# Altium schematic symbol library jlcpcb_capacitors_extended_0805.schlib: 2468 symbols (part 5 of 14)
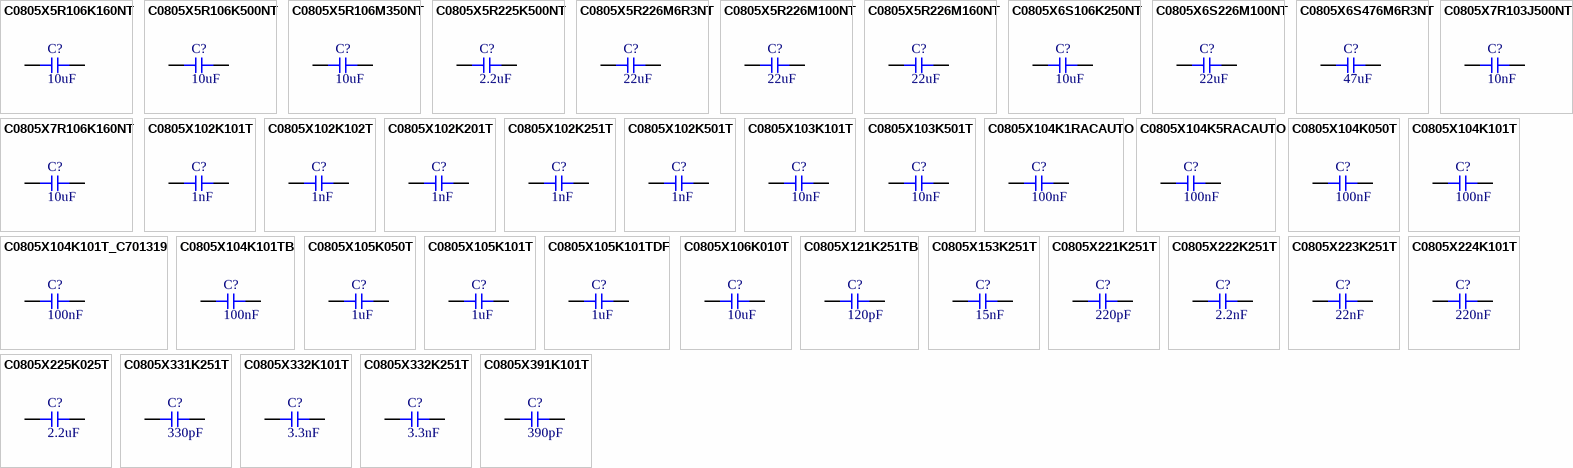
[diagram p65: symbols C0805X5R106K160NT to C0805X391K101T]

## C0805X5R106K500NT
designator C?  Capacitance: 10uF  (hidden comment: *)
Capacitor, Ceramic (MLCC), 10uF, ±10%, 50V, ±10%, SMD 0805; Manufacturer: SANYEAR; Manufacturer Part Number: C0805X5R106K500NT
footprint CAP-0805 (0805 (2012M) Capacitor)
pins: 1, 2

## C0805X5R106M350NT
designator C?  Capacitance: 10uF  (hidden comment: *)
Capacitor, Ceramic (MLCC), 10uF, ±20%, 35V, ±20%, SMD 0805; Manufacturer: SANYEAR; Manufacturer Part Number: C0805X5R106M350NT
footprint CAP-0805 (0805 (2012M) Capacitor)
pins: 1, 2

## C0805X5R225K500NT
designator C?  Capacitance: 2.2uF  (hidden comment: *)
Capacitor, Ceramic (MLCC), 2.2uF, ±10%, 50V, X5R, ±10%, SMD 0805; Manufacturer: SANYEAR; Manufacturer Part Number: C0805X5R225K500NT
footprint CAP-0805 (0805 (2012M) Capacitor)
pins: 1, 2

## C0805X5R226M6R3NT
designator C?  Capacitance: 22uF  (hidden comment: *)
Capacitor, Ceramic (MLCC), 22uF, ±20%, 6.3V, X5R, ±20%, SMD 0805; Manufacturer: SANYEAR; Manufacturer Part Number: C0805X5R226M6R3NT
footprint CAP-0805 (0805 (2012M) Capacitor)
pins: 1, 2

## C0805X5R226M100NT
designator C?  Capacitance: 22uF  (hidden comment: *)
Capacitor, Ceramic (MLCC), 22uF, ±20%, 10V, X5R, ±20%, SMD 0805; Manufacturer: SANYEAR; Manufacturer Part Number: C0805X5R226M100NT
footprint CAP-0805 (0805 (2012M) Capacitor)
pins: 1, 2

## C0805X5R226M160NT
designator C?  Capacitance: 22uF  (hidden comment: *)
Capacitor, Ceramic (MLCC), 22uF, ±20%, 16V, X5R, ±20%, SMD 0805; Manufacturer: SANYEAR; Manufacturer Part Number: C0805X5R226M160NT
footprint CAP-0805 (0805 (2012M) Capacitor)
pins: 1, 2

## C0805X6S106K250NT
designator C?  Capacitance: 10uF  (hidden comment: *)
Capacitor, Ceramic (MLCC), 10uF, ±10%, 25V, ±10%, SMD 0805; Manufacturer: SANYEAR; Manufacturer Part Number: C0805X6S106K250NT
footprint CAP-0805 (0805 (2012M) Capacitor)
pins: 1, 2

## C0805X6S226M100NT
designator C?  Capacitance: 22uF  (hidden comment: *)
Capacitor, Ceramic (MLCC), 22uF, ±20%, 10V, ±20%, SMD 0805; Manufacturer: SANYEAR; Manufacturer Part Number: C0805X6S226M100NT
footprint CAP-0805 (0805 (2012M) Capacitor)
pins: 1, 2

## C0805X6S476M6R3NT
designator C?  Capacitance: 47uF  (hidden comment: *)
Capacitor, Ceramic (MLCC), 47uF, ±20%, 6.3V, ±20%, SMD 0805; Manufacturer: SANYEAR; Manufacturer Part Number: C0805X6S476M6R3NT
footprint CAP-0805 (0805 (2012M) Capacitor)
pins: 1, 2

## C0805X7R103J500NT
designator C?  Capacitance: 10nF  (hidden comment: *)
Capacitor, Ceramic (MLCC), 10nF, ±5%, 50V, ±5%, SMD 0805; Manufacturer: SANYEAR; Manufacturer Part Number: C0805X7R103J500NT
footprint CAP-0805 (0805 (2012M) Capacitor)
pins: 1, 2

## C0805X7R106K160NT
designator C?  Capacitance: 10uF  (hidden comment: *)
Capacitor, Ceramic (MLCC), 10uF, ±10%, 16V, ±10%, SMD 0805; Manufacturer: SANYEAR; Manufacturer Part Number: C0805X7R106K160NT
footprint CAP-0805 (0805 (2012M) Capacitor)
pins: 1, 2

## C0805X102K101T
designator C?  Capacitance: 1nF  (hidden comment: *)
Capacitor, Ceramic (MLCC), 1nF, ±10%, 100V, X7R, ±10%, SMD 0805; Manufacturer: IHHEC(HOLY STONE ENTERPRISE CO., LTD); Manufacturer Part Number: C0805X102K101T
footprint CAP-0805 (0805 (2012M) Capacitor)
pins: 1, 2

## C0805X102K102T
designator C?  Capacitance: 1nF  (hidden comment: *)
Capacitor, Ceramic (MLCC), 1nF, ±10%, 1kV, X7R, ±10%, SMD 0805; Manufacturer: IHHEC(HOLY STONE ENTERPRISE CO., LTD); Manufacturer Part Number: C0805X102K102T
footprint CAP-0805 (0805 (2012M) Capacitor)
pins: 1, 2

## C0805X102K201T
designator C?  Capacitance: 1nF  (hidden comment: *)
Capacitor, Ceramic (MLCC), 1nF, ±10%, 200V, X7R, ±10%, SMD 0805; Manufacturer: IHHEC(HOLY STONE ENTERPRISE CO., LTD); Manufacturer Part Number: C0805X102K201T
footprint CAP-0805 (0805 (2012M) Capacitor)
pins: 1, 2

## C0805X102K251T
designator C?  Capacitance: 1nF  (hidden comment: *)
Capacitor, Ceramic (MLCC), 1nF, ±10%, 250V, X7R, ±10%, SMD 0805; Manufacturer: IHHEC(HOLY STONE ENTERPRISE CO., LTD); Manufacturer Part Number: C0805X102K251T
footprint CAP-0805 (0805 (2012M) Capacitor)
pins: 1, 2

## C0805X102K501T
designator C?  Capacitance: 1nF  (hidden comment: *)
Capacitor, Ceramic (MLCC), 1nF, ±10%, 500V, X7R, ±10%, SMD 0805; Manufacturer: IHHEC(HOLY STONE ENTERPRISE CO., LTD); Manufacturer Part Number: C0805X102K501T
footprint CAP-0805 (0805 (2012M) Capacitor)
pins: 1, 2

## C0805X103K101T
designator C?  Capacitance: 10nF  (hidden comment: *)
Capacitor, Ceramic (MLCC), 10nF, ±10%, 100V, X7R, ±10%, SMD 0805; Manufacturer: IHHEC(HOLY STONE ENTERPRISE CO., LTD); Manufacturer Part Number: C0805X103K101T
footprint CAP-0805 (0805 (2012M) Capacitor)
pins: 1, 2

## C0805X103K501T
designator C?  Capacitance: 10nF  (hidden comment: *)
Capacitor, Ceramic (MLCC), 10nF, ±10%, 500V, X7R, ±10%, SMD 0805; Manufacturer: IHHEC(HOLY STONE ENTERPRISE CO., LTD); Manufacturer Part Number: C0805X103K501T
footprint CAP-0805 (0805 (2012M) Capacitor)
pins: 1, 2

## C0805X104K1RACAUTO
designator C?  Capacitance: 100nF  (hidden comment: *)
Capacitor, Ceramic (MLCC), 100nF, ±10%, 100V, X7R, ±10%, SMD 0805; Manufacturer: KEMET; Manufacturer Part Number: C0805X104K1RACAUTO
footprint CAP-0805 (0805 (2012M) Capacitor)
pins: 1, 2

## C0805X104K5RACAUTO
designator C?  Capacitance: 100nF  (hidden comment: *)
Capacitor, Ceramic (MLCC), 100nF, ±10%, 50V, X7R, ±10%, SMD 0805; Manufacturer: KEMET; Manufacturer Part Number: C0805X104K5RACAUTO
footprint CAP-0805 (0805 (2012M) Capacitor)
pins: 1, 2

## C0805X104K050T
designator C?  Capacitance: 100nF  (hidden comment: *)
Capacitor, Ceramic (MLCC), 100nF, ±10%, 50V, X7R, ±10%, SMD 0805; Manufacturer: IHHEC(HOLY STONE ENTERPRISE CO., LTD); Manufacturer Part Number: C0805X104K050T
footprint CAP-0805 (0805 (2012M) Capacitor)
pins: 1, 2

## C0805X104K101T
designator C?  Capacitance: 100nF  (hidden comment: *)
Capacitor, Ceramic (MLCC), 100nF, ±10%, 100V, X7R, ±10%, SMD 0805; Manufacturer: IHHEC(HOLY STONE ENTERPRISE CO., LTD); Manufacturer Part Number: C0805X104K101T
footprint CAP-0805 (0805 (2012M) Capacitor)
pins: 1, 2

## C0805X104K101T_C701319
designator C?  Capacitance: 100nF  (hidden comment: *)
Capacitor, Ceramic (MLCC), 100nF, ±10%, 100V, X7R, ±10%, SMD 0805; Manufacturer: IHHEC(HOLY STONE ENTERPRISE CO., LTD); Manufacturer Part Number: C0805X104K101T
footprint CAP-0805 (0805 (2012M) Capacitor)
pins: 1, 2

## C0805X104K101TB
designator C?  Capacitance: 100nF  (hidden comment: *)
Capacitor, Ceramic (MLCC), 100nF, ±10%, 100V, ±10%, SMD 0805; Manufacturer: IHHEC(HOLY STONE ENTERPRISE CO., LTD); Manufacturer Part Number: C0805X104K101TB
footprint CAP-0805 (0805 (2012M) Capacitor)
pins: 1, 2

## C0805X105K050T
designator C?  Capacitance: 1uF  (hidden comment: *)
Capacitor, Ceramic (MLCC), 1uF, ±10%, 50V, X7R, ±10%, SMD 0805; Manufacturer: IHHEC(HOLY STONE ENTERPRISE CO., LTD); Manufacturer Part Number: C0805X105K050T
footprint CAP-0805 (0805 (2012M) Capacitor)
pins: 1, 2

## C0805X105K101T
designator C?  Capacitance: 1uF  (hidden comment: *)
Capacitor, Ceramic (MLCC), 1uF, ±10%, 100V, X7R, ±10%, SMD 0805; Manufacturer: IHHEC(HOLY STONE ENTERPRISE CO., LTD); Manufacturer Part Number: C0805X105K101T
footprint CAP-0805 (0805 (2012M) Capacitor)
pins: 1, 2

## C0805X105K101TDF
designator C?  Capacitance: 1uF  (hidden comment: *)
Capacitor, Ceramic (MLCC), 1uF, ±10%, 100V, X7R, ±10%, SMD 0805; Manufacturer: IHHEC(HOLY STONE ENTERPRISE CO., LTD); Manufacturer Part Number: C0805X105K101TDF
footprint CAP-0805 (0805 (2012M) Capacitor)
pins: 1, 2

## C0805X106K010T
designator C?  Capacitance: 10uF  (hidden comment: *)
Capacitor, Ceramic (MLCC), 10uF, ±10%, 10V, X7R, ±10%, SMD 0805; Manufacturer: IHHEC(HOLY STONE ENTERPRISE CO., LTD); Manufacturer Part Number: C0805X106K010T
footprint CAP-0805 (0805 (2012M) Capacitor)
pins: 1, 2

## C0805X121K251TB
designator C?  Capacitance: 120pF  (hidden comment: *)
Capacitor, Ceramic (MLCC), 120pF, ±10%, 250V, X7R, ±10%, SMD 0805; Manufacturer: IHHEC(HOLY STONE ENTERPRISE CO., LTD); Manufacturer Part Number: C0805X121K251TB
footprint CAP-0805 (0805 (2012M) Capacitor)
pins: 1, 2

## C0805X153K251T
designator C?  Capacitance: 15nF  (hidden comment: *)
Capacitor, Ceramic (MLCC), 15nF, ±10%, 250V, X7R, ±10%, SMD 0805; Manufacturer: IHHEC(HOLY STONE ENTERPRISE CO., LTD); Manufacturer Part Number: C0805X153K251T
footprint CAP-0805 (0805 (2012M) Capacitor)
pins: 1, 2

## C0805X221K251T
designator C?  Capacitance: 220pF  (hidden comment: *)
Capacitor, Ceramic (MLCC), 220pF, ±10%, 250V, X7R, ±10%, SMD 0805; Manufacturer: IHHEC(HOLY STONE ENTERPRISE CO., LTD); Manufacturer Part Number: C0805X221K251T
footprint CAP-0805 (0805 (2012M) Capacitor)
pins: 1, 2

## C0805X222K251T
designator C?  Capacitance: 2.2nF  (hidden comment: *)
Capacitor, Ceramic (MLCC), 2.2nF, ±10%, 250V, X7R, ±10%, SMD 0805; Manufacturer: IHHEC(HOLY STONE ENTERPRISE CO., LTD); Manufacturer Part Number: C0805X222K251T
footprint CAP-0805 (0805 (2012M) Capacitor)
pins: 1, 2

## C0805X223K251T
designator C?  Capacitance: 22nF  (hidden comment: *)
Capacitor, Ceramic (MLCC), 22nF, ±10%, 250V, X7R, ±10%, SMD 0805; Manufacturer: IHHEC(HOLY STONE ENTERPRISE CO., LTD); Manufacturer Part Number: C0805X223K251T
footprint CAP-0805 (0805 (2012M) Capacitor)
pins: 1, 2

## C0805X224K101T
designator C?  Capacitance: 220nF  (hidden comment: *)
Capacitor, Ceramic (MLCC), 220nF, ±10%, 100V, X7R, ±10%, SMD 0805; Manufacturer: IHHEC(HOLY STONE ENTERPRISE CO., LTD); Manufacturer Part Number: C0805X224K101T
footprint CAP-0805 (0805 (2012M) Capacitor)
pins: 1, 2

## C0805X225K025T
designator C?  Capacitance: 2.2uF  (hidden comment: *)
Capacitor, Ceramic (MLCC), 2.2uF, ±10%, 25V, X7R, ±10%, SMD 0805; Manufacturer: IHHEC(HOLY STONE ENTERPRISE CO., LTD); Manufacturer Part Number: C0805X225K025T
footprint CAP-0805 (0805 (2012M) Capacitor)
pins: 1, 2

## C0805X331K251T
designator C?  Capacitance: 330pF  (hidden comment: *)
Capacitor, Ceramic (MLCC), 330pF, ±10%, 250V, X7R, ±10%, SMD 0805; Manufacturer: IHHEC(HOLY STONE ENTERPRISE CO., LTD); Manufacturer Part Number: C0805X331K251T
footprint CAP-0805 (0805 (2012M) Capacitor)
pins: 1, 2

## C0805X332K101T
designator C?  Capacitance: 3.3nF  (hidden comment: *)
Capacitor, Ceramic (MLCC), 3.3nF, ±10%, 100V, X7R, ±10%, SMD 0805; Manufacturer: IHHEC(HOLY STONE ENTERPRISE CO., LTD); Manufacturer Part Number: C0805X332K101T
footprint CAP-0805 (0805 (2012M) Capacitor)
pins: 1, 2

## C0805X332K251T
designator C?  Capacitance: 3.3nF  (hidden comment: *)
Capacitor, Ceramic (MLCC), 3.3nF, ±10%, 250V, X7R, ±10%, SMD 0805; Manufacturer: IHHEC(HOLY STONE ENTERPRISE CO., LTD); Manufacturer Part Number: C0805X332K251T
footprint CAP-0805 (0805 (2012M) Capacitor)
pins: 1, 2

## C0805X391K101T
designator C?  Capacitance: 390pF  (hidden comment: *)
Capacitor, Ceramic (MLCC), 390pF, ±10%, 100V, X7R, ±10%, SMD 0805; Manufacturer: IHHEC(HOLY STONE ENTERPRISE CO., LTD); Manufacturer Part Number: C0805X391K101T
footprint CAP-0805 (0805 (2012M) Capacitor)
pins: 1, 2

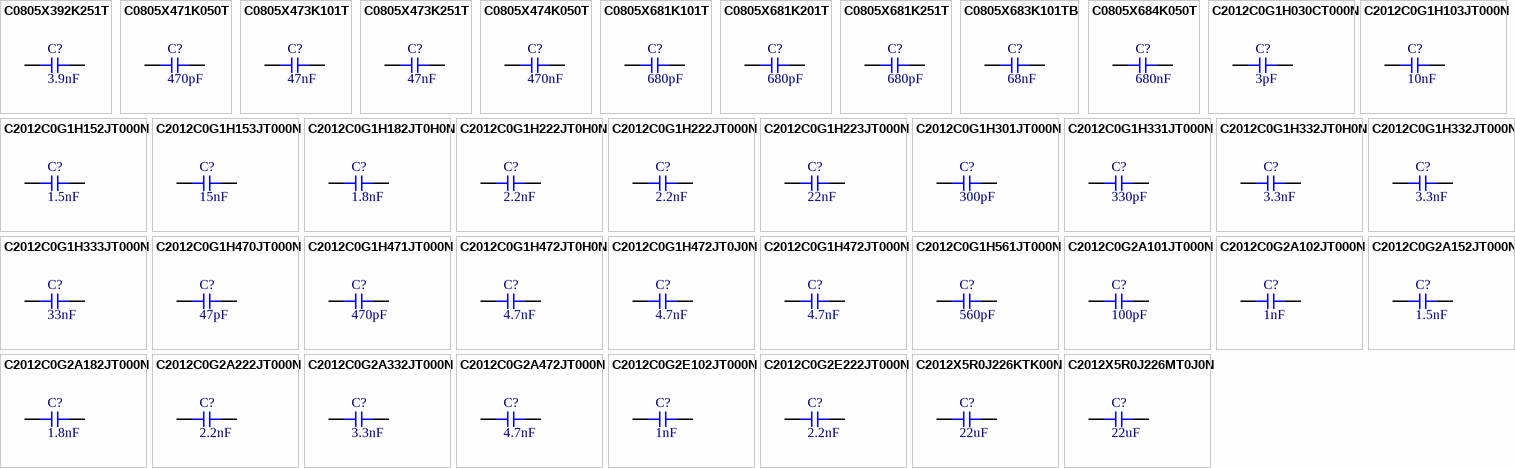
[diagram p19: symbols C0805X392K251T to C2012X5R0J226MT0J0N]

## C0805X392K251T
designator C?  Capacitance: 3.9nF  (hidden comment: *)
Capacitor, Ceramic (MLCC), 3.9nF, ±10%, 250V, X7R, ±10%, SMD 0805; Manufacturer: IHHEC(HOLY STONE ENTERPRISE CO., LTD); Manufacturer Part Number: C0805X392K251T
footprint CAP-0805 (0805 (2012M) Capacitor)
pins: 1, 2

## C0805X471K050T
designator C?  Capacitance: 470pF  (hidden comment: *)
Capacitor, Ceramic (MLCC), 470pF, ±10%, 50V, X7R, ±10%, SMD 0805; Manufacturer: IHHEC(HOLY STONE ENTERPRISE CO., LTD); Manufacturer Part Number: C0805X471K050T
footprint CAP-0805 (0805 (2012M) Capacitor)
pins: 1, 2

## C0805X473K101T
designator C?  Capacitance: 47nF  (hidden comment: *)
Capacitor, Ceramic (MLCC), 47nF, ±10%, 100V, X7R, ±10%, SMD 0805; Manufacturer: IHHEC(HOLY STONE ENTERPRISE CO., LTD); Manufacturer Part Number: C0805X473K101T
footprint CAP-0805 (0805 (2012M) Capacitor)
pins: 1, 2

## C0805X473K251T
designator C?  Capacitance: 47nF  (hidden comment: *)
Capacitor, Ceramic (MLCC), 47nF, ±10%, 250V, X7R, ±10%, SMD 0805; Manufacturer: IHHEC(HOLY STONE ENTERPRISE CO., LTD); Manufacturer Part Number: C0805X473K251T
footprint CAP-0805 (0805 (2012M) Capacitor)
pins: 1, 2

## C0805X474K050T
designator C?  Capacitance: 470nF  (hidden comment: *)
Capacitor, Ceramic (MLCC), 470nF, ±10%, 50V, X7R, ±10%, SMD 0805; Manufacturer: IHHEC(HOLY STONE ENTERPRISE CO., LTD); Manufacturer Part Number: C0805X474K050T
footprint CAP-0805 (0805 (2012M) Capacitor)
pins: 1, 2

## C0805X681K101T
designator C?  Capacitance: 680pF  (hidden comment: *)
Capacitor, Ceramic (MLCC), 680pF, ±10%, 100V, X7R, ±10%, SMD 0805; Manufacturer: IHHEC(HOLY STONE ENTERPRISE CO., LTD); Manufacturer Part Number: C0805X681K101T
footprint CAP-0805 (0805 (2012M) Capacitor)
pins: 1, 2

## C0805X681K201T
designator C?  Capacitance: 680pF  (hidden comment: *)
Capacitor, Ceramic (MLCC), 680pF, ±10%, 200V, X7R, ±10%, SMD 0805; Manufacturer: IHHEC(HOLY STONE ENTERPRISE CO., LTD); Manufacturer Part Number: C0805X681K201T
footprint CAP-0805 (0805 (2012M) Capacitor)
pins: 1, 2

## C0805X681K251T
designator C?  Capacitance: 680pF  (hidden comment: *)
Capacitor, Ceramic (MLCC), 680pF, ±10%, 250V, X7R, ±10%, SMD 0805; Manufacturer: IHHEC(HOLY STONE ENTERPRISE CO., LTD); Manufacturer Part Number: C0805X681K251T
footprint CAP-0805 (0805 (2012M) Capacitor)
pins: 1, 2

## C0805X683K101TB
designator C?  Capacitance: 68nF  (hidden comment: *)
Capacitor, Ceramic (MLCC), 68nF, ±10%, 100V, X7R, ±10%, SMD 0805; Manufacturer: IHHEC(HOLY STONE ENTERPRISE CO., LTD); Manufacturer Part Number: C0805X683K101TB
footprint CAP-0805 (0805 (2012M) Capacitor)
pins: 1, 2

## C0805X684K050T
designator C?  Capacitance: 680nF  (hidden comment: *)
Capacitor, Ceramic (MLCC), 680nF, ±10%, 50V, X7R, ±10%, SMD 0805; Manufacturer: IHHEC(HOLY STONE ENTERPRISE CO., LTD); Manufacturer Part Number: C0805X684K050T
footprint CAP-0805 (0805 (2012M) Capacitor)
pins: 1, 2

## C2012C0G1H030CT000N
designator C?  Capacitance: 3pF  (hidden comment: *)
Capacitor, Ceramic (MLCC), 3pF, ±0.25pF, 50V, C0G, ±0.25pF, SMD 0805; Manufacturer: TDK; Manufacturer Part Number: C2012C0G1H030CT000N
footprint CAP-0805 (0805 (2012M) Capacitor)
pins: 1, 2

## C2012C0G1H103JT000N
designator C?  Capacitance: 10nF  (hidden comment: *)
Capacitor, Ceramic (MLCC), 10nF, ±5%, 50V, C0G, ±5%, SMD 0805; Manufacturer: TDK; Manufacturer Part Number: C2012C0G1H103JT000N
footprint CAP-0805 (0805 (2012M) Capacitor)
pins: 1, 2

## C2012C0G1H152JT000N
designator C?  Capacitance: 1.5nF  (hidden comment: *)
Capacitor, Ceramic (MLCC), 1.5nF, ±5%, 50V, C0G, ±5%, SMD 0805; Manufacturer: TDK; Manufacturer Part Number: C2012C0G1H152JT000N
footprint CAP-0805 (0805 (2012M) Capacitor)
pins: 1, 2

## C2012C0G1H153JT000N
designator C?  Capacitance: 15nF  (hidden comment: *)
Capacitor, Ceramic (MLCC), 15nF, ±5%, 50V, C0G, ±5%, SMD 0805; Manufacturer: TDK; Manufacturer Part Number: C2012C0G1H153JT000N
footprint CAP-0805 (0805 (2012M) Capacitor)
pins: 1, 2

## C2012C0G1H182JT0H0N
designator C?  Capacitance: 1.8nF  (hidden comment: *)
Capacitor, Ceramic (MLCC), 1.8nF, ±5%, 50V, C0G, ±5%, SMD 0805; Manufacturer: TDK; Manufacturer Part Number: C2012C0G1H182JT0H0N
footprint CAP-0805 (0805 (2012M) Capacitor)
pins: 1, 2

## C2012C0G1H222JT0H0N
designator C?  Capacitance: 2.2nF  (hidden comment: *)
Capacitor, Ceramic (MLCC), 2.2nF, ±5%, 50V, C0G, ±5%, SMD 0805; Manufacturer: TDK; Manufacturer Part Number: C2012C0G1H222JT0H0N
footprint CAP-0805 (0805 (2012M) Capacitor)
pins: 1, 2

## C2012C0G1H222JT000N
designator C?  Capacitance: 2.2nF  (hidden comment: *)
Capacitor, Ceramic (MLCC), 2.2nF, ±5%, 50V, C0G, ±5%, SMD 0805; Manufacturer: TDK; Manufacturer Part Number: C2012C0G1H222JT000N
footprint CAP-0805 (0805 (2012M) Capacitor)
pins: 1, 2

## C2012C0G1H223JT000N
designator C?  Capacitance: 22nF  (hidden comment: *)
Capacitor, Ceramic (MLCC), 22nF, ±5%, 50V, C0G, ±5%, SMD 0805; Manufacturer: TDK; Manufacturer Part Number: C2012C0G1H223JT000N
footprint CAP-0805 (0805 (2012M) Capacitor)
pins: 1, 2

## C2012C0G1H301JT000N
designator C?  Capacitance: 300pF  (hidden comment: *)
Capacitor, Ceramic (MLCC), 300pF, ±5%, 50V, C0G, ±5%, SMD 0805; Manufacturer: TDK; Manufacturer Part Number: C2012C0G1H301JT000N
footprint CAP-0805 (0805 (2012M) Capacitor)
pins: 1, 2

## C2012C0G1H331JT000N
designator C?  Capacitance: 330pF  (hidden comment: *)
Capacitor, Ceramic (MLCC), 330pF, ±5%, 50V, C0G, ±5%, SMD 0805; Manufacturer: TDK; Manufacturer Part Number: C2012C0G1H331JT000N
footprint CAP-0805 (0805 (2012M) Capacitor)
pins: 1, 2

## C2012C0G1H332JT0H0N
designator C?  Capacitance: 3.3nF  (hidden comment: *)
Capacitor, Ceramic (MLCC), 3.3nF, ±5%, 50V, C0G, ±5%, SMD 0805; Manufacturer: TDK; Manufacturer Part Number: C2012C0G1H332JT0H0N
footprint CAP-0805 (0805 (2012M) Capacitor)
pins: 1, 2

## C2012C0G1H332JT000N
designator C?  Capacitance: 3.3nF  (hidden comment: *)
Capacitor, Ceramic (MLCC), 3.3nF, ±5%, 50V, C0G, ±5%, SMD 0805; Manufacturer: TDK; Manufacturer Part Number: C2012C0G1H332JT000N
footprint CAP-0805 (0805 (2012M) Capacitor)
pins: 1, 2

## C2012C0G1H333JT000N
designator C?  Capacitance: 33nF  (hidden comment: *)
Capacitor, Ceramic (MLCC), 33nF, ±5%, 50V, C0G, ±5%, SMD 0805; Manufacturer: TDK; Manufacturer Part Number: C2012C0G1H333JT000N
footprint CAP-0805 (0805 (2012M) Capacitor)
pins: 1, 2

## C2012C0G1H470JT000N
designator C?  Capacitance: 47pF  (hidden comment: *)
Capacitor, Ceramic (MLCC), 47pF, ±5%, 50V, C0G, ±5%, SMD 0805; Manufacturer: TDK; Manufacturer Part Number: C2012C0G1H470JT000N
footprint CAP-0805 (0805 (2012M) Capacitor)
pins: 1, 2

## C2012C0G1H471JT000N
designator C?  Capacitance: 470pF  (hidden comment: *)
Capacitor, Ceramic (MLCC), 470pF, ±5%, 50V, C0G, ±5%, SMD 0805; Manufacturer: TDK; Manufacturer Part Number: C2012C0G1H471JT000N
footprint CAP-0805 (0805 (2012M) Capacitor)
pins: 1, 2

## C2012C0G1H472JT0H0N
designator C?  Capacitance: 4.7nF  (hidden comment: *)
Capacitor, Ceramic (MLCC), 4.7nF, ±5%, 50V, C0G, ±5%, SMD 0805; Manufacturer: TDK; Manufacturer Part Number: C2012C0G1H472JT0H0N
footprint CAP-0805 (0805 (2012M) Capacitor)
pins: 1, 2

## C2012C0G1H472JT0J0N
designator C?  Capacitance: 4.7nF  (hidden comment: *)
Capacitor, Ceramic (MLCC), 4.7nF, ±5%, 50V, C0G, ±5%, SMD 0805; Manufacturer: TDK; Manufacturer Part Number: C2012C0G1H472JT0J0N
footprint CAP-0805 (0805 (2012M) Capacitor)
pins: 1, 2

## C2012C0G1H472JT000N
designator C?  Capacitance: 4.7nF  (hidden comment: *)
Capacitor, Ceramic (MLCC), 4.7nF, ±5%, 50V, C0G, ±5%, SMD 0805; Manufacturer: TDK; Manufacturer Part Number: C2012C0G1H472JT000N
footprint CAP-0805 (0805 (2012M) Capacitor)
pins: 1, 2

## C2012C0G1H561JT000N
designator C?  Capacitance: 560pF  (hidden comment: *)
Capacitor, Ceramic (MLCC), 560pF, ±5%, 50V, C0G, ±5%, SMD 0805; Manufacturer: TDK; Manufacturer Part Number: C2012C0G1H561JT000N
footprint CAP-0805 (0805 (2012M) Capacitor)
pins: 1, 2

## C2012C0G2A101JT000N
designator C?  Capacitance: 100pF  (hidden comment: *)
Capacitor, Ceramic (MLCC), 100pF, ±5%, 100V, C0G, ±5%, SMD 0805; Manufacturer: TDK; Manufacturer Part Number: C2012C0G2A101JT000N
footprint CAP-0805 (0805 (2012M) Capacitor)
pins: 1, 2

## C2012C0G2A102JT000N
designator C?  Capacitance: 1nF  (hidden comment: *)
Capacitor, Ceramic (MLCC), 1nF, ±5%, 100V, C0G, ±5%, SMD 0805; Manufacturer: TDK; Manufacturer Part Number: C2012C0G2A102JT000N
footprint CAP-0805 (0805 (2012M) Capacitor)
pins: 1, 2

## C2012C0G2A152JT000N
designator C?  Capacitance: 1.5nF  (hidden comment: *)
Capacitor, Ceramic (MLCC), 1.5nF, ±5%, 100V, C0G, ±5%, SMD 0805; Manufacturer: TDK; Manufacturer Part Number: C2012C0G2A152JT000N
footprint CAP-0805 (0805 (2012M) Capacitor)
pins: 1, 2

## C2012C0G2A182JT000N
designator C?  Capacitance: 1.8nF  (hidden comment: *)
Capacitor, Ceramic (MLCC), 1.8nF, ±5%, 100V, C0G, ±5%, SMD 0805; Manufacturer: TDK; Manufacturer Part Number: C2012C0G2A182JT000N
footprint CAP-0805 (0805 (2012M) Capacitor)
pins: 1, 2

## C2012C0G2A222JT000N
designator C?  Capacitance: 2.2nF  (hidden comment: *)
Capacitor, Ceramic (MLCC), 2.2nF, ±5%, 100V, C0G, ±5%, SMD 0805; Manufacturer: TDK; Manufacturer Part Number: C2012C0G2A222JT000N
footprint CAP-0805 (0805 (2012M) Capacitor)
pins: 1, 2

## C2012C0G2A332JT000N
designator C?  Capacitance: 3.3nF  (hidden comment: *)
Capacitor, Ceramic (MLCC), 3.3nF, ±5%, 100V, C0G, ±5%, SMD 0805; Manufacturer: TDK; Manufacturer Part Number: C2012C0G2A332JT000N
footprint CAP-0805 (0805 (2012M) Capacitor)
pins: 1, 2

## C2012C0G2A472JT000N
designator C?  Capacitance: 4.7nF  (hidden comment: *)
Capacitor, Ceramic (MLCC), 4.7nF, ±5%, 100V, C0G, ±5%, SMD 0805; Manufacturer: TDK; Manufacturer Part Number: C2012C0G2A472JT000N
footprint CAP-0805 (0805 (2012M) Capacitor)
pins: 1, 2

## C2012C0G2E102JT000N
designator C?  Capacitance: 1nF  (hidden comment: *)
Capacitor, Ceramic (MLCC), 1nF, ±5%, 250V, C0G, ±5%, SMD 0805; Manufacturer: TDK; Manufacturer Part Number: C2012C0G2E102JT000N
footprint CAP-0805 (0805 (2012M) Capacitor)
pins: 1, 2

## C2012C0G2E222JT000N
designator C?  Capacitance: 2.2nF  (hidden comment: *)
Capacitor, Ceramic (MLCC), 2.2nF, ±5%, 250V, C0G, ±5%, SMD 0805; Manufacturer: TDK; Manufacturer Part Number: C2012C0G2E222JT000N
footprint CAP-0805 (0805 (2012M) Capacitor)
pins: 1, 2

## C2012X5R0J226KTK00N
designator C?  Capacitance: 22uF  (hidden comment: *)
Capacitor, Ceramic (MLCC), 22uF, ±10%, 6.3V, X5R, ±10%, SMD 0805; Manufacturer: TDK; Manufacturer Part Number: C2012X5R0J226KTK00N
footprint CAP-0805 (0805 (2012M) Capacitor)
pins: 1, 2

## C2012X5R0J226MT0J0N
designator C?  Capacitance: 22uF  (hidden comment: *)
Capacitor, Ceramic (MLCC), 22uF, ±20%, 6.3V, X5R, ±20%, SMD 0805; Manufacturer: TDK; Manufacturer Part Number: C2012X5R0J226MT0J0N
footprint CAP-0805 (0805 (2012M) Capacitor)
pins: 1, 2

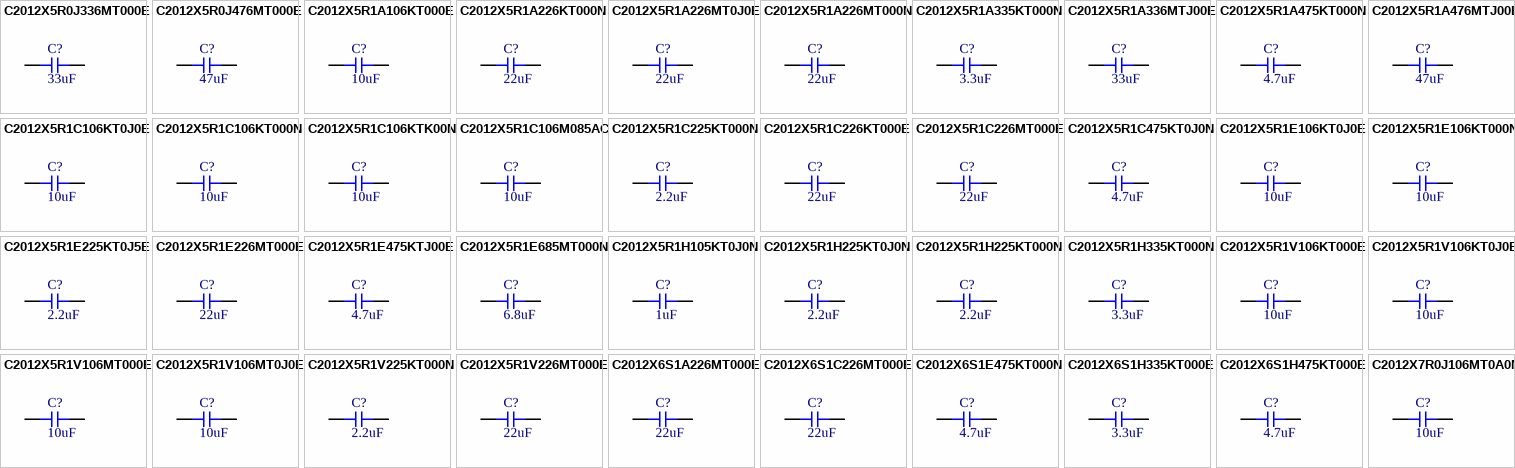
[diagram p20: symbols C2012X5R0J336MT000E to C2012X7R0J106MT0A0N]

## C2012X5R0J336MT000E
designator C?  Capacitance: 33uF  (hidden comment: *)
Capacitor, Ceramic (MLCC), 33uF, ±20%, 6.3V, X5R, ±20%, SMD 0805; Manufacturer: TDK; Manufacturer Part Number: C2012X5R0J336MT000E
footprint CAP-0805 (0805 (2012M) Capacitor)
pins: 1, 2

## C2012X5R0J476MT000E
designator C?  Capacitance: 47uF  (hidden comment: *)
Capacitor, Ceramic (MLCC), 47uF, ±20%, 6.3V, X5R, ±20%, SMD 0805; Manufacturer: TDK; Manufacturer Part Number: C2012X5R0J476MT000E
footprint CAP-0805 (0805 (2012M) Capacitor)
pins: 1, 2

## C2012X5R1A106KT000E
designator C?  Capacitance: 10uF  (hidden comment: *)
Capacitor, Ceramic (MLCC), 10uF, ±10%, 10V, X5R, ±10%, SMD 0805; Manufacturer: TDK; Manufacturer Part Number: C2012X5R1A106KT000E
footprint CAP-0805 (0805 (2012M) Capacitor)
pins: 1, 2

## C2012X5R1A226KT000N
designator C?  Capacitance: 22uF  (hidden comment: *)
Capacitor, Ceramic (MLCC), 22uF, ±10%, 10V, X5R, ±10%, SMD 0805; Manufacturer: TDK; Manufacturer Part Number: C2012X5R1A226KT000N
footprint CAP-0805 (0805 (2012M) Capacitor)
pins: 1, 2

## C2012X5R1A226MT0J0E
designator C?  Capacitance: 22uF  (hidden comment: *)
Capacitor, Ceramic (MLCC), 22uF, ±20%, 10V, X5R, ±20%, SMD 0805; Manufacturer: TDK; Manufacturer Part Number: C2012X5R1A226MT0J0E
footprint CAP-0805 (0805 (2012M) Capacitor)
pins: 1, 2

## C2012X5R1A226MT000N
designator C?  Capacitance: 22uF  (hidden comment: *)
Capacitor, Ceramic (MLCC), 22uF, ±20%, 10V, X5R, ±20%, SMD 0805; Manufacturer: TDK; Manufacturer Part Number: C2012X5R1A226MT000N
footprint CAP-0805 (0805 (2012M) Capacitor)
pins: 1, 2

## C2012X5R1A335KT000N
designator C?  Capacitance: 3.3uF  (hidden comment: *)
Capacitor, Ceramic (MLCC), 3.3uF, ±10%, 10V, X5R, ±10%, SMD 0805; Manufacturer: TDK; Manufacturer Part Number: C2012X5R1A335KT000N
footprint CAP-0805 (0805 (2012M) Capacitor)
pins: 1, 2

## C2012X5R1A336MTJ00E
designator C?  Capacitance: 33uF  (hidden comment: *)
Capacitor, Ceramic (MLCC), 33uF, ±20%, 10V, X5R, ±20%, SMD 0805; Manufacturer: TDK; Manufacturer Part Number: C2012X5R1A336MTJ00E
footprint CAP-0805 (0805 (2012M) Capacitor)
pins: 1, 2

## C2012X5R1A475KT000N
designator C?  Capacitance: 4.7uF  (hidden comment: *)
Capacitor, Ceramic (MLCC), 4.7uF, ±10%, 10V, X5R, ±10%, SMD 0805; Manufacturer: TDK; Manufacturer Part Number: C2012X5R1A475KT000N
footprint CAP-0805 (0805 (2012M) Capacitor)
pins: 1, 2

## C2012X5R1A476MTJ00E
designator C?  Capacitance: 47uF  (hidden comment: *)
Capacitor, Ceramic (MLCC), 47uF, ±20%, 10V, X5R, ±20%, SMD 0805; Manufacturer: TDK; Manufacturer Part Number: C2012X5R1A476MTJ00E
footprint CAP-0805 (0805 (2012M) Capacitor)
pins: 1, 2

## C2012X5R1C106KT0J0E
designator C?  Capacitance: 10uF  (hidden comment: *)
Capacitor, Ceramic (MLCC), 10uF, ±10%, 16V, X5R, ±10%, SMD 0805; Manufacturer: TDK; Manufacturer Part Number: C2012X5R1C106KT0J0E
footprint CAP-0805 (0805 (2012M) Capacitor)
pins: 1, 2

## C2012X5R1C106KT000N
designator C?  Capacitance: 10uF  (hidden comment: *)
Capacitor, Ceramic (MLCC), 10uF, ±10%, 16V, X5R, ±10%, SMD 0805; Manufacturer: TDK; Manufacturer Part Number: C2012X5R1C106KT000N
footprint CAP-0805 (0805 (2012M) Capacitor)
pins: 1, 2

## C2012X5R1C106KTK00N
designator C?  Capacitance: 10uF  (hidden comment: *)
Capacitor, Ceramic (MLCC), 10uF, ±10%, 16V, X5R, ±10%, SMD 0805; Manufacturer: TDK; Manufacturer Part Number: C2012X5R1C106KTK00N
footprint CAP-0805 (0805 (2012M) Capacitor)
pins: 1, 2

## C2012X5R1C106M085AC
designator C?  Capacitance: 10uF  (hidden comment: *)
Capacitor, Ceramic (MLCC), 10uF, ±20%, 16V, X5R, ±20%, SMD 0805; Manufacturer: TDK; Manufacturer Part Number: C2012X5R1C106M085AC
footprint CAP-0805 (0805 (2012M) Capacitor)
pins: 1, 2

## C2012X5R1C225KT000N
designator C?  Capacitance: 2.2uF  (hidden comment: *)
Capacitor, Ceramic (MLCC), 2.2uF, ±10%, 16V, X5R, ±10%, SMD 0805; Manufacturer: TDK; Manufacturer Part Number: C2012X5R1C225KT000N
footprint CAP-0805 (0805 (2012M) Capacitor)
pins: 1, 2

## C2012X5R1C226KT000E
designator C?  Capacitance: 22uF  (hidden comment: *)
Capacitor, Ceramic (MLCC), 22uF, ±10%, 16V, X5R, ±10%, SMD 0805; Manufacturer: TDK; Manufacturer Part Number: C2012X5R1C226KT000E
footprint CAP-0805 (0805 (2012M) Capacitor)
pins: 1, 2

## C2012X5R1C226MT000E
designator C?  Capacitance: 22uF  (hidden comment: *)
Capacitor, Ceramic (MLCC), 22uF, ±20%, 16V, X5R, ±20%, SMD 0805; Manufacturer: TDK; Manufacturer Part Number: C2012X5R1C226MT000E
footprint CAP-0805 (0805 (2012M) Capacitor)
pins: 1, 2

## C2012X5R1C475KT0J0N
designator C?  Capacitance: 4.7uF  (hidden comment: *)
Capacitor, Ceramic (MLCC), 4.7uF, ±10%, 16V, X5R, ±10%, SMD 0805; Manufacturer: TDK; Manufacturer Part Number: C2012X5R1C475KT0J0N
footprint CAP-0805 (0805 (2012M) Capacitor)
pins: 1, 2

## C2012X5R1E106KT0J0E
designator C?  Capacitance: 10uF  (hidden comment: *)
Capacitor, Ceramic (MLCC), 10uF, ±10%, 25V, X5R, ±10%, SMD 0805; Manufacturer: TDK; Manufacturer Part Number: C2012X5R1E106KT0J0E
footprint CAP-0805 (0805 (2012M) Capacitor)
pins: 1, 2

## C2012X5R1E106KT000N
designator C?  Capacitance: 10uF  (hidden comment: *)
Capacitor, Ceramic (MLCC), 10uF, ±10%, 25V, X5R, ±10%, SMD 0805; Manufacturer: TDK; Manufacturer Part Number: C2012X5R1E106KT000N
footprint CAP-0805 (0805 (2012M) Capacitor)
pins: 1, 2

## C2012X5R1E225KT0J5E
designator C?  Capacitance: 2.2uF  (hidden comment: *)
Capacitor, Ceramic (MLCC), 2.2uF, ±10%, 25V, X5R, ±10%, SMD 0805; Manufacturer: TDK; Manufacturer Part Number: C2012X5R1E225KT0J5E
footprint CAP-0805 (0805 (2012M) Capacitor)
pins: 1, 2

## C2012X5R1E226MT000E
designator C?  Capacitance: 22uF  (hidden comment: *)
Capacitor, Ceramic (MLCC), 22uF, ±20%, 25V, X5R, ±20%, SMD 0805; Manufacturer: TDK; Manufacturer Part Number: C2012X5R1E226MT000E
footprint CAP-0805 (0805 (2012M) Capacitor)
pins: 1, 2

## C2012X5R1E475KTJ00E
designator C?  Capacitance: 4.7uF  (hidden comment: *)
Capacitor, Ceramic (MLCC), 4.7uF, ±10%, 25V, X5R, ±10%, SMD 0805; Manufacturer: TDK; Manufacturer Part Number: C2012X5R1E475KTJ00E
footprint CAP-0805 (0805 (2012M) Capacitor)
pins: 1, 2

## C2012X5R1E685MT000N
designator C?  Capacitance: 6.8uF  (hidden comment: *)
Capacitor, Ceramic (MLCC), 6.8uF, ±20%, 25V, X5R, ±20%, SMD 0805; Manufacturer: TDK; Manufacturer Part Number: C2012X5R1E685MT000N
footprint CAP-0805 (0805 (2012M) Capacitor)
pins: 1, 2

## C2012X5R1H105KT0J0N
designator C?  Capacitance: 1uF  (hidden comment: *)
Capacitor, Ceramic (MLCC), 1uF, ±10%, 50V, X5R, ±10%, SMD 0805; Manufacturer: TDK; Manufacturer Part Number: C2012X5R1H105KT0J0N
footprint CAP-0805 (0805 (2012M) Capacitor)
pins: 1, 2

## C2012X5R1H225KT0J0N
designator C?  Capacitance: 2.2uF  (hidden comment: *)
Capacitor, Ceramic (MLCC), 2.2uF, ±10%, 50V, X5R, ±10%, SMD 0805; Manufacturer: TDK; Manufacturer Part Number: C2012X5R1H225KT0J0N
footprint CAP-0805 (0805 (2012M) Capacitor)
pins: 1, 2

## C2012X5R1H225KT000N
designator C?  Capacitance: 2.2uF  (hidden comment: *)
Capacitor, Ceramic (MLCC), 2.2uF, ±10%, 50V, X5R, ±10%, SMD 0805; Manufacturer: TDK; Manufacturer Part Number: C2012X5R1H225KT000N
footprint CAP-0805 (0805 (2012M) Capacitor)
pins: 1, 2

## C2012X5R1H335KT000N
designator C?  Capacitance: 3.3uF  (hidden comment: *)
Capacitor, Ceramic (MLCC), 3.3uF, ±10%, 50V, X5R, ±10%, SMD 0805; Manufacturer: TDK; Manufacturer Part Number: C2012X5R1H335KT000N
footprint CAP-0805 (0805 (2012M) Capacitor)
pins: 1, 2

## C2012X5R1V106KT000E
designator C?  Capacitance: 10uF  (hidden comment: *)
Capacitor, Ceramic (MLCC), 10uF, ±10%, 35V, X5R, ±10%, SMD 0805; Manufacturer: TDK; Manufacturer Part Number: C2012X5R1V106KT000E
footprint CAP-0805 (0805 (2012M) Capacitor)
pins: 1, 2

## C2012X5R1V106KT0J0E
designator C?  Capacitance: 10uF  (hidden comment: *)
Capacitor, Ceramic (MLCC), 10uF, ±10%, 35V, X5R, ±10%, SMD 0805; Manufacturer: TDK; Manufacturer Part Number: C2012X5R1V106KT0J0E
footprint CAP-0805 (0805 (2012M) Capacitor)
pins: 1, 2

## C2012X5R1V106MT000E
designator C?  Capacitance: 10uF  (hidden comment: *)
Capacitor, Ceramic (MLCC), 10uF, ±20%, 35V, X5R, ±20%, SMD 0805; Manufacturer: TDK; Manufacturer Part Number: C2012X5R1V106MT000E
footprint CAP-0805 (0805 (2012M) Capacitor)
pins: 1, 2

## C2012X5R1V106MT0J0E
designator C?  Capacitance: 10uF  (hidden comment: *)
Capacitor, Ceramic (MLCC), 10uF, ±20%, 35V, X5R, ±20%, SMD 0805; Manufacturer: TDK; Manufacturer Part Number: C2012X5R1V106MT0J0E
footprint CAP-0805 (0805 (2012M) Capacitor)
pins: 1, 2

## C2012X5R1V225KT000N
designator C?  Capacitance: 2.2uF  (hidden comment: *)
Capacitor, Ceramic (MLCC), 2.2uF, ±10%, 35V, X5R, ±10%, SMD 0805; Manufacturer: TDK; Manufacturer Part Number: C2012X5R1V225KT000N
footprint CAP-0805 (0805 (2012M) Capacitor)
pins: 1, 2

## C2012X5R1V226MT000E
designator C?  Capacitance: 22uF  (hidden comment: *)
Capacitor, Ceramic (MLCC), 22uF, ±20%, 35V, X5R, ±20%, SMD 0805; Manufacturer: TDK; Manufacturer Part Number: C2012X5R1V226MT000E
footprint CAP-0805 (0805 (2012M) Capacitor)
pins: 1, 2

## C2012X6S1A226MT000E
designator C?  Capacitance: 22uF  (hidden comment: *)
Capacitor, Ceramic (MLCC), 22uF, ±20%, 10V, X6S, ±20%, SMD 0805; Manufacturer: TDK; Manufacturer Part Number: C2012X6S1A226MT000E
footprint CAP-0805 (0805 (2012M) Capacitor)
pins: 1, 2

## C2012X6S1C226MT000E
designator C?  Capacitance: 22uF  (hidden comment: *)
Capacitor, Ceramic (MLCC), 22uF, ±20%, 16V, X6S, ±20%, SMD 0805; Manufacturer: TDK; Manufacturer Part Number: C2012X6S1C226MT000E
footprint CAP-0805 (0805 (2012M) Capacitor)
pins: 1, 2

## C2012X6S1E475KT000N
designator C?  Capacitance: 4.7uF  (hidden comment: *)
Capacitor, Ceramic (MLCC), 4.7uF, ±10%, 25V, X6S, ±10%, SMD 0805; Manufacturer: TDK; Manufacturer Part Number: C2012X6S1E475KT000N
footprint CAP-0805 (0805 (2012M) Capacitor)
pins: 1, 2

## C2012X6S1H335KT000E
designator C?  Capacitance: 3.3uF  (hidden comment: *)
Capacitor, Ceramic (MLCC), 3.3uF, ±10%, 50V, X6S, ±10%, SMD 0805; Manufacturer: TDK; Manufacturer Part Number: C2012X6S1H335KT000E
footprint CAP-0805 (0805 (2012M) Capacitor)
pins: 1, 2

## C2012X6S1H475KT000E
designator C?  Capacitance: 4.7uF  (hidden comment: *)
Capacitor, Ceramic (MLCC), 4.7uF, ±10%, 50V, X6S, ±10%, SMD 0805; Manufacturer: TDK; Manufacturer Part Number: C2012X6S1H475KT000E
footprint CAP-0805 (0805 (2012M) Capacitor)
pins: 1, 2

## C2012X7R0J106MT0A0N
designator C?  Capacitance: 10uF  (hidden comment: *)
Capacitor, Ceramic (MLCC), 10uF, ±20%, 6.3V, X7R, ±20%, SMD 0805; Manufacturer: TDK; Manufacturer Part Number: C2012X7R0J106MT0A0N
footprint CAP-0805 (0805 (2012M) Capacitor)
pins: 1, 2

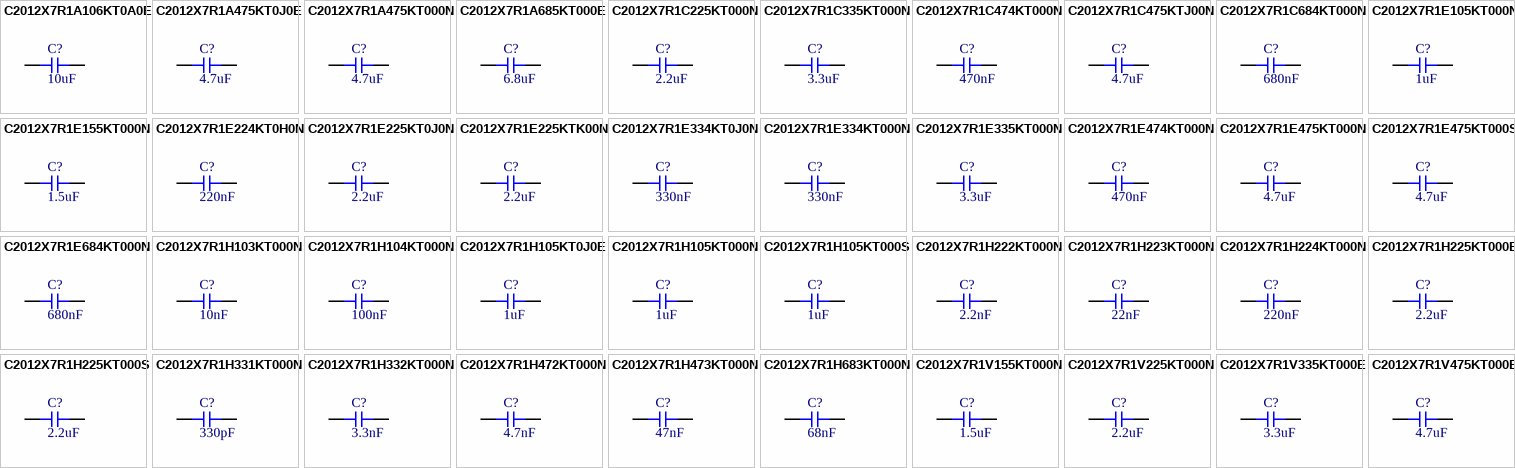
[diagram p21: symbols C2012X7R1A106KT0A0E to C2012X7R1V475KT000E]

## C2012X7R1A106KT0A0E
designator C?  Capacitance: 10uF  (hidden comment: *)
Capacitor, Ceramic (MLCC), 10uF, ±10%, 10V, X7R, ±10%, SMD 0805; Manufacturer: TDK; Manufacturer Part Number: C2012X7R1A106KT0A0E
footprint CAP-0805 (0805 (2012M) Capacitor)
pins: 1, 2

## C2012X7R1A475KT0J0E
designator C?  Capacitance: 4.7uF  (hidden comment: *)
Capacitor, Ceramic (MLCC), 4.7uF, ±10%, 10V, X7R, ±10%, SMD 0805; Manufacturer: TDK; Manufacturer Part Number: C2012X7R1A475KT0J0E
footprint CAP-0805 (0805 (2012M) Capacitor)
pins: 1, 2

## C2012X7R1A475KT000N
designator C?  Capacitance: 4.7uF  (hidden comment: *)
Capacitor, Ceramic (MLCC), 4.7uF, ±10%, 10V, X7R, ±10%, SMD 0805; Manufacturer: TDK; Manufacturer Part Number: C2012X7R1A475KT000N
footprint CAP-0805 (0805 (2012M) Capacitor)
pins: 1, 2

## C2012X7R1A685KT000E
designator C?  Capacitance: 6.8uF  (hidden comment: *)
Capacitor, Ceramic (MLCC), 6.8uF, ±10%, 10V, X7R, ±10%, SMD 0805; Manufacturer: TDK; Manufacturer Part Number: C2012X7R1A685KT000E
footprint CAP-0805 (0805 (2012M) Capacitor)
pins: 1, 2

## C2012X7R1C225KT000N
designator C?  Capacitance: 2.2uF  (hidden comment: *)
Capacitor, Ceramic (MLCC), 2.2uF, ±10%, 16V, X7R, ±10%, SMD 0805; Manufacturer: TDK; Manufacturer Part Number: C2012X7R1C225KT000N
footprint CAP-0805 (0805 (2012M) Capacitor)
pins: 1, 2

## C2012X7R1C335KT000N
designator C?  Capacitance: 3.3uF  (hidden comment: *)
Capacitor, Ceramic (MLCC), 3.3uF, ±10%, 16V, X7R, ±10%, SMD 0805; Manufacturer: TDK; Manufacturer Part Number: C2012X7R1C335KT000N
footprint CAP-0805 (0805 (2012M) Capacitor)
pins: 1, 2

## C2012X7R1C474KT000N
designator C?  Capacitance: 470nF  (hidden comment: *)
Capacitor, Ceramic (MLCC), 470nF, ±10%, 16V, X7R, ±10%, SMD 0805; Manufacturer: TDK; Manufacturer Part Number: C2012X7R1C474KT000N
footprint CAP-0805 (0805 (2012M) Capacitor)
pins: 1, 2

## C2012X7R1C475KTJ00N
designator C?  Capacitance: 4.7uF  (hidden comment: *)
Capacitor, Ceramic (MLCC), 4.7uF, ±10%, 16V, X7R, ±10%, SMD 0805; Manufacturer: TDK; Manufacturer Part Number: C2012X7R1C475KTJ00N
footprint CAP-0805 (0805 (2012M) Capacitor)
pins: 1, 2

## C2012X7R1C684KT000N
designator C?  Capacitance: 680nF  (hidden comment: *)
Capacitor, Ceramic (MLCC), 680nF, ±10%, 16V, X7R, ±10%, SMD 0805; Manufacturer: TDK; Manufacturer Part Number: C2012X7R1C684KT000N
footprint CAP-0805 (0805 (2012M) Capacitor)
pins: 1, 2

## C2012X7R1E105KT000N
designator C?  Capacitance: 1uF  (hidden comment: *)
Capacitor, Ceramic (MLCC), 1uF, ±10%, 25V, X7R, ±10%, SMD 0805; Manufacturer: TDK; Manufacturer Part Number: C2012X7R1E105KT000N
footprint CAP-0805 (0805 (2012M) Capacitor)
pins: 1, 2

## C2012X7R1E155KT000N
designator C?  Capacitance: 1.5uF  (hidden comment: *)
Capacitor, Ceramic (MLCC), 1.5uF, ±10%, 25V, X7R, ±10%, SMD 0805; Manufacturer: TDK; Manufacturer Part Number: C2012X7R1E155KT000N
footprint CAP-0805 (0805 (2012M) Capacitor)
pins: 1, 2

## C2012X7R1E224KT0H0N
designator C?  Capacitance: 220nF  (hidden comment: *)
Capacitor, Ceramic (MLCC), 220nF, ±10%, 25V, X7R, ±10%, SMD 0805; Manufacturer: TDK; Manufacturer Part Number: C2012X7R1E224KT0H0N
footprint CAP-0805 (0805 (2012M) Capacitor)
pins: 1, 2

## C2012X7R1E225KT0J0N
designator C?  Capacitance: 2.2uF  (hidden comment: *)
Capacitor, Ceramic (MLCC), 2.2uF, ±10%, 25V, X7R, ±10%, SMD 0805; Manufacturer: TDK; Manufacturer Part Number: C2012X7R1E225KT0J0N
footprint CAP-0805 (0805 (2012M) Capacitor)
pins: 1, 2

## C2012X7R1E225KTK00N
designator C?  Capacitance: 2.2uF  (hidden comment: *)
Capacitor, Ceramic (MLCC), 2.2uF, ±10%, 25V, X7R, ±10%, SMD 0805; Manufacturer: TDK; Manufacturer Part Number: C2012X7R1E225KTK00N
footprint CAP-0805 (0805 (2012M) Capacitor)
pins: 1, 2

## C2012X7R1E334KT0J0N
designator C?  Capacitance: 330nF  (hidden comment: *)
Capacitor, Ceramic (MLCC), 330nF, ±10%, 25V, X7R, ±10%, SMD 0805; Manufacturer: TDK; Manufacturer Part Number: C2012X7R1E334KT0J0N
footprint CAP-0805 (0805 (2012M) Capacitor)
pins: 1, 2

## C2012X7R1E334KT000N
designator C?  Capacitance: 330nF  (hidden comment: *)
Capacitor, Ceramic (MLCC), 330nF, ±10%, 25V, X7R, ±10%, SMD 0805; Manufacturer: TDK; Manufacturer Part Number: C2012X7R1E334KT000N
footprint CAP-0805 (0805 (2012M) Capacitor)
pins: 1, 2

## C2012X7R1E335KT000N
designator C?  Capacitance: 3.3uF  (hidden comment: *)
Capacitor, Ceramic (MLCC), 3.3uF, ±10%, 25V, X7R, ±10%, SMD 0805; Manufacturer: TDK; Manufacturer Part Number: C2012X7R1E335KT000N
footprint CAP-0805 (0805 (2012M) Capacitor)
pins: 1, 2

## C2012X7R1E474KT000N
designator C?  Capacitance: 470nF  (hidden comment: *)
Capacitor, Ceramic (MLCC), 470nF, ±10%, 25V, X7R, ±10%, SMD 0805; Manufacturer: TDK; Manufacturer Part Number: C2012X7R1E474KT000N
footprint CAP-0805 (0805 (2012M) Capacitor)
pins: 1, 2

## C2012X7R1E475KT000N
designator C?  Capacitance: 4.7uF  (hidden comment: *)
Capacitor, Ceramic (MLCC), 4.7uF, ±10%, 25V, X7R, ±10%, SMD 0805; Manufacturer: TDK; Manufacturer Part Number: C2012X7R1E475KT000N
footprint CAP-0805 (0805 (2012M) Capacitor)
pins: 1, 2

## C2012X7R1E475KT000S
designator C?  Capacitance: 4.7uF  (hidden comment: *)
Capacitor, Ceramic (MLCC), 4.7uF, ±10%, 25V, X7R, ±10%, SMD 0805; Manufacturer: TDK; Manufacturer Part Number: C2012X7R1E475KT000S
footprint CAP-0805 (0805 (2012M) Capacitor)
pins: 1, 2

## C2012X7R1E684KT000N
designator C?  Capacitance: 680nF  (hidden comment: *)
Capacitor, Ceramic (MLCC), 680nF, ±10%, 25V, X7R, ±10%, SMD 0805; Manufacturer: TDK; Manufacturer Part Number: C2012X7R1E684KT000N
footprint CAP-0805 (0805 (2012M) Capacitor)
pins: 1, 2

## C2012X7R1H103KT000N
designator C?  Capacitance: 10nF  (hidden comment: *)
Capacitor, Ceramic (MLCC), 10nF, ±10%, 50V, X7R, ±10%, SMD 0805; Manufacturer: TDK; Manufacturer Part Number: C2012X7R1H103KT000N
footprint CAP-0805 (0805 (2012M) Capacitor)
pins: 1, 2

## C2012X7R1H104KT000N
designator C?  Capacitance: 100nF  (hidden comment: *)
Capacitor, Ceramic (MLCC), 100nF, ±10%, 50V, X7R, ±10%, SMD 0805; Manufacturer: TDK; Manufacturer Part Number: C2012X7R1H104KT000N
footprint CAP-0805 (0805 (2012M) Capacitor)
pins: 1, 2

## C2012X7R1H105KT0J0E
designator C?  Capacitance: 1uF  (hidden comment: *)
Capacitor, Ceramic (MLCC), 1uF, ±10%, 50V, X7R, ±10%, SMD 0805; Manufacturer: TDK; Manufacturer Part Number: C2012X7R1H105KT0J0E
footprint CAP-0805 (0805 (2012M) Capacitor)
pins: 1, 2

## C2012X7R1H105KT000N
designator C?  Capacitance: 1uF  (hidden comment: *)
Capacitor, Ceramic (MLCC), 1uF, ±10%, 50V, X7R, ±10%, SMD 0805; Manufacturer: TDK; Manufacturer Part Number: C2012X7R1H105KT000N
footprint CAP-0805 (0805 (2012M) Capacitor)
pins: 1, 2

## C2012X7R1H105KT000S
designator C?  Capacitance: 1uF  (hidden comment: *)
Capacitor, Ceramic (MLCC), 1uF, ±10%, 50V, X7R, ±10%, SMD 0805; Manufacturer: TDK; Manufacturer Part Number: C2012X7R1H105KT000S
footprint CAP-0805 (0805 (2012M) Capacitor)
pins: 1, 2

## C2012X7R1H222KT000N
designator C?  Capacitance: 2.2nF  (hidden comment: *)
Capacitor, Ceramic (MLCC), 2.2nF, ±10%, 50V, X7R, ±10%, SMD 0805; Manufacturer: TDK; Manufacturer Part Number: C2012X7R1H222KT000N
footprint CAP-0805 (0805 (2012M) Capacitor)
pins: 1, 2

## C2012X7R1H223KT000N
designator C?  Capacitance: 22nF  (hidden comment: *)
Capacitor, Ceramic (MLCC), 22nF, ±10%, 50V, X7R, ±10%, SMD 0805; Manufacturer: TDK; Manufacturer Part Number: C2012X7R1H223KT000N
footprint CAP-0805 (0805 (2012M) Capacitor)
pins: 1, 2

## C2012X7R1H224KT000N
designator C?  Capacitance: 220nF  (hidden comment: *)
Capacitor, Ceramic (MLCC), 220nF, ±10%, 50V, X7R, ±10%, SMD 0805; Manufacturer: TDK; Manufacturer Part Number: C2012X7R1H224KT000N
footprint CAP-0805 (0805 (2012M) Capacitor)
pins: 1, 2

## C2012X7R1H225KT000E
designator C?  Capacitance: 2.2uF  (hidden comment: *)
Capacitor, Ceramic (MLCC), 2.2uF, ±10%, 50V, X7R, ±10%, SMD 0805; Manufacturer: TDK; Manufacturer Part Number: C2012X7R1H225KT000E
footprint CAP-0805 (0805 (2012M) Capacitor)
pins: 1, 2

## C2012X7R1H225KT000S
designator C?  Capacitance: 2.2uF  (hidden comment: *)
Capacitor, Ceramic (MLCC), 2.2uF, ±10%, 50V, X7R, ±10%, SMD 0805; Manufacturer: TDK; Manufacturer Part Number: C2012X7R1H225KT000S
footprint CAP-0805 (0805 (2012M) Capacitor)
pins: 1, 2

## C2012X7R1H331KT000N
designator C?  Capacitance: 330pF  (hidden comment: *)
Capacitor, Ceramic (MLCC), 330pF, ±10%, 50V, X7R, ±10%, SMD 0805; Manufacturer: TDK; Manufacturer Part Number: C2012X7R1H331KT000N
footprint CAP-0805 (0805 (2012M) Capacitor)
pins: 1, 2

## C2012X7R1H332KT000N
designator C?  Capacitance: 3.3nF  (hidden comment: *)
Capacitor, Ceramic (MLCC), 3.3nF, ±10%, 50V, X7R, ±10%, SMD 0805; Manufacturer: TDK; Manufacturer Part Number: C2012X7R1H332KT000N
footprint CAP-0805 (0805 (2012M) Capacitor)
pins: 1, 2

## C2012X7R1H472KT000N
designator C?  Capacitance: 4.7nF  (hidden comment: *)
Capacitor, Ceramic (MLCC), 4.7nF, ±10%, 50V, X7R, ±10%, SMD 0805; Manufacturer: TDK; Manufacturer Part Number: C2012X7R1H472KT000N
footprint CAP-0805 (0805 (2012M) Capacitor)
pins: 1, 2

## C2012X7R1H473KT000N
designator C?  Capacitance: 47nF  (hidden comment: *)
Capacitor, Ceramic (MLCC), 47nF, ±10%, 50V, X7R, ±10%, SMD 0805; Manufacturer: TDK; Manufacturer Part Number: C2012X7R1H473KT000N
footprint CAP-0805 (0805 (2012M) Capacitor)
pins: 1, 2

## C2012X7R1H683KT000N
designator C?  Capacitance: 68nF  (hidden comment: *)
Capacitor, Ceramic (MLCC), 68nF, ±10%, 50V, X7R, ±10%, SMD 0805; Manufacturer: TDK; Manufacturer Part Number: C2012X7R1H683KT000N
footprint CAP-0805 (0805 (2012M) Capacitor)
pins: 1, 2

## C2012X7R1V155KT000N
designator C?  Capacitance: 1.5uF  (hidden comment: *)
Capacitor, Ceramic (MLCC), 1.5uF, ±10%, 35V, X7R, ±10%, SMD 0805; Manufacturer: TDK; Manufacturer Part Number: C2012X7R1V155KT000N
footprint CAP-0805 (0805 (2012M) Capacitor)
pins: 1, 2

## C2012X7R1V225KT000N
designator C?  Capacitance: 2.2uF  (hidden comment: *)
Capacitor, Ceramic (MLCC), 2.2uF, ±10%, 35V, X7R, ±10%, SMD 0805; Manufacturer: TDK; Manufacturer Part Number: C2012X7R1V225KT000N
footprint CAP-0805 (0805 (2012M) Capacitor)
pins: 1, 2

## C2012X7R1V335KT000E
designator C?  Capacitance: 3.3uF  (hidden comment: *)
Capacitor, Ceramic (MLCC), 3.3uF, ±10%, 35V, X7R, ±10%, SMD 0805; Manufacturer: TDK; Manufacturer Part Number: C2012X7R1V335KT000E
footprint CAP-0805 (0805 (2012M) Capacitor)
pins: 1, 2

## C2012X7R1V475KT000E
designator C?  Capacitance: 4.7uF  (hidden comment: *)
Capacitor, Ceramic (MLCC), 4.7uF, ±10%, 35V, X7R, ±10%, SMD 0805; Manufacturer: TDK; Manufacturer Part Number: C2012X7R1V475KT000E
footprint CAP-0805 (0805 (2012M) Capacitor)
pins: 1, 2

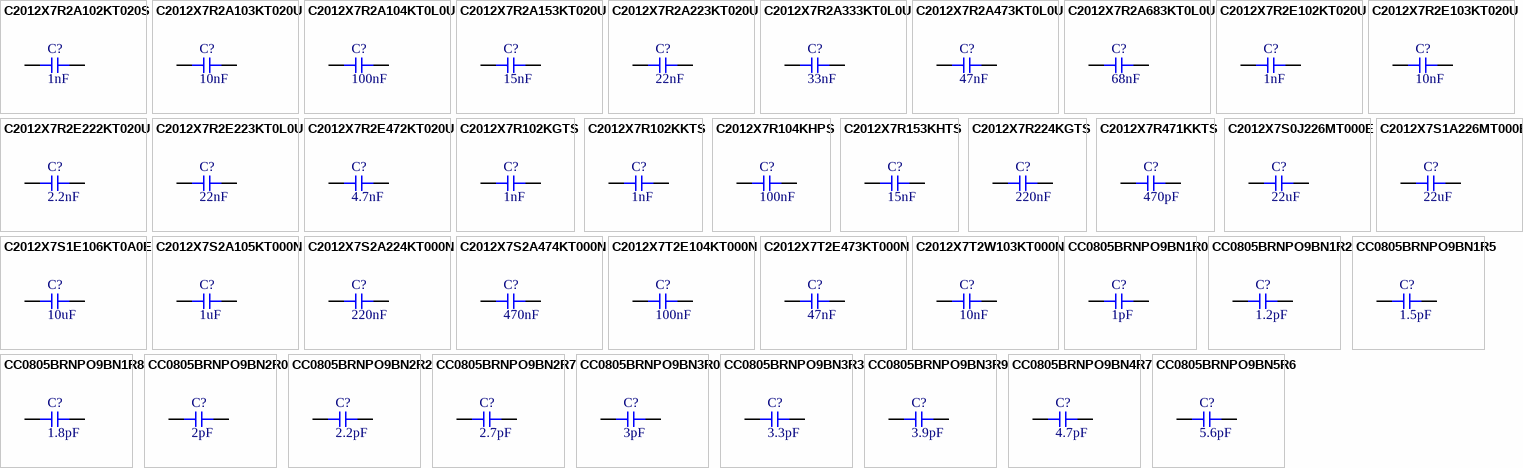
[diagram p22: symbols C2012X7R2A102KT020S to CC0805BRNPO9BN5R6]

## C2012X7R2A102KT020S
designator C?  Capacitance: 1nF  (hidden comment: *)
Capacitor, Ceramic (MLCC), 1nF, ±10%, 100V, X7R, ±10%, SMD 0805; Manufacturer: TDK; Manufacturer Part Number: C2012X7R2A102KT020S
footprint CAP-0805 (0805 (2012M) Capacitor)
pins: 1, 2

## C2012X7R2A103KT020U
designator C?  Capacitance: 10nF  (hidden comment: *)
Capacitor, Ceramic (MLCC), 10nF, ±10%, 100V, X7R, ±10%, SMD 0805; Manufacturer: TDK; Manufacturer Part Number: C2012X7R2A103KT020U
footprint CAP-0805 (0805 (2012M) Capacitor)
pins: 1, 2

## C2012X7R2A104KT0L0U
designator C?  Capacitance: 100nF  (hidden comment: *)
Capacitor, Ceramic (MLCC), 100nF, ±10%, 100V, X7R, ±10%, SMD 0805; Manufacturer: TDK; Manufacturer Part Number: C2012X7R2A104KT0L0U
footprint CAP-0805 (0805 (2012M) Capacitor)
pins: 1, 2

## C2012X7R2A153KT020U
designator C?  Capacitance: 15nF  (hidden comment: *)
Capacitor, Ceramic (MLCC), 15nF, ±10%, 100V, X7R, ±10%, SMD 0805; Manufacturer: TDK; Manufacturer Part Number: C2012X7R2A153KT020U
footprint CAP-0805 (0805 (2012M) Capacitor)
pins: 1, 2

## C2012X7R2A223KT020U
designator C?  Capacitance: 22nF  (hidden comment: *)
Capacitor, Ceramic (MLCC), 22nF, ±10%, 100V, X7R, ±10%, SMD 0805; Manufacturer: TDK; Manufacturer Part Number: C2012X7R2A223KT020U
footprint CAP-0805 (0805 (2012M) Capacitor)
pins: 1, 2

## C2012X7R2A333KT0L0U
designator C?  Capacitance: 33nF  (hidden comment: *)
Capacitor, Ceramic (MLCC), 33nF, ±10%, 100V, X7R, ±10%, SMD 0805; Manufacturer: TDK; Manufacturer Part Number: C2012X7R2A333KT0L0U
footprint CAP-0805 (0805 (2012M) Capacitor)
pins: 1, 2

## C2012X7R2A473KT0L0U
designator C?  Capacitance: 47nF  (hidden comment: *)
Capacitor, Ceramic (MLCC), 47nF, ±10%, 100V, X7R, ±10%, SMD 0805; Manufacturer: TDK; Manufacturer Part Number: C2012X7R2A473KT0L0U
footprint CAP-0805 (0805 (2012M) Capacitor)
pins: 1, 2

## C2012X7R2A683KT0L0U
designator C?  Capacitance: 68nF  (hidden comment: *)
Capacitor, Ceramic (MLCC), 68nF, ±10%, 100V, X7R, ±10%, SMD 0805; Manufacturer: TDK; Manufacturer Part Number: C2012X7R2A683KT0L0U
footprint CAP-0805 (0805 (2012M) Capacitor)
pins: 1, 2

## C2012X7R2E102KT020U
designator C?  Capacitance: 1nF  (hidden comment: *)
Capacitor, Ceramic (MLCC), 1nF, ±10%, 250V, X7R, ±10%, SMD 0805; Manufacturer: TDK; Manufacturer Part Number: C2012X7R2E102KT020U
footprint CAP-0805 (0805 (2012M) Capacitor)
pins: 1, 2

## C2012X7R2E103KT020U
designator C?  Capacitance: 10nF  (hidden comment: *)
Capacitor, Ceramic (MLCC), 10nF, ±10%, 250V, X7R, ±10%, SMD 0805; Manufacturer: TDK; Manufacturer Part Number: C2012X7R2E103KT020U
footprint CAP-0805 (0805 (2012M) Capacitor)
pins: 1, 2

## C2012X7R2E222KT020U
designator C?  Capacitance: 2.2nF  (hidden comment: *)
Capacitor, Ceramic (MLCC), 2.2nF, ±10%, 250V, X7R, ±10%, SMD 0805; Manufacturer: TDK; Manufacturer Part Number: C2012X7R2E222KT020U
footprint CAP-0805 (0805 (2012M) Capacitor)
pins: 1, 2

## C2012X7R2E223KT0L0U
designator C?  Capacitance: 22nF  (hidden comment: *)
Capacitor, Ceramic (MLCC), 22nF, ±10%, 250V, X7R, ±10%, SMD 0805; Manufacturer: TDK; Manufacturer Part Number: C2012X7R2E223KT0L0U
footprint CAP-0805 (0805 (2012M) Capacitor)
pins: 1, 2

## C2012X7R2E472KT020U
designator C?  Capacitance: 4.7nF  (hidden comment: *)
Capacitor, Ceramic (MLCC), 4.7nF, ±10%, 250V, X7R, ±10%, SMD 0805; Manufacturer: TDK; Manufacturer Part Number: C2012X7R2E472KT020U
footprint CAP-0805 (0805 (2012M) Capacitor)
pins: 1, 2

## C2012X7R102KGTS
designator C?  Capacitance: 1nF  (hidden comment: *)
Capacitor, Ceramic (MLCC), 1nF, ±10%, 50V, X7R, ±10%, SMD 0805; Manufacturer: Darfon Elec; Manufacturer Part Number: C2012X7R102KGTS
footprint CAP-0805 (0805 (2012M) Capacitor)
pins: 1, 2

## C2012X7R102KKTS
designator C?  Capacitance: 1nF  (hidden comment: *)
Capacitor, Ceramic (MLCC), 1nF, ±10%, 250V, X7R, ±10%, SMD 0805; Manufacturer: Darfon Elec; Manufacturer Part Number: C2012X7R102KKTS
footprint CAP-0805 (0805 (2012M) Capacitor)
pins: 1, 2

## C2012X7R104KHPS
designator C?  Capacitance: 100nF  (hidden comment: *)
Capacitor, Ceramic (MLCC), 100nF, ±10%, 100V, X7R, ±10%, SMD 0805; Manufacturer: Darfon Elec; Manufacturer Part Number: C2012X7R104KHPS
footprint CAP-0805 (0805 (2012M) Capacitor)
pins: 1, 2

## C2012X7R153KHTS
designator C?  Capacitance: 15nF  (hidden comment: *)
Capacitor, Ceramic (MLCC), 15nF, ±10%, 100V, X7R, ±10%, SMD 0805; Manufacturer: Darfon Elec; Manufacturer Part Number: C2012X7R153KHTS
footprint CAP-0805 (0805 (2012M) Capacitor)
pins: 1, 2

## C2012X7R224KGTS
designator C?  Capacitance: 220nF  (hidden comment: *)
Capacitor, Ceramic (MLCC), 220nF, ±10%, 50V, X7R, ±10%, SMD 0805; Manufacturer: Darfon Elec; Manufacturer Part Number: C2012X7R224KGTS
footprint CAP-0805 (0805 (2012M) Capacitor)
pins: 1, 2

## C2012X7R471KKTS
designator C?  Capacitance: 470pF  (hidden comment: *)
Capacitor, Ceramic (MLCC), 470pF, ±10%, 250V, X7R, ±10%, SMD 0805; Manufacturer: Darfon Elec; Manufacturer Part Number: C2012X7R471KKTS
footprint CAP-0805 (0805 (2012M) Capacitor)
pins: 1, 2

## C2012X7S0J226MT000E
designator C?  Capacitance: 22uF  (hidden comment: *)
Capacitor, Ceramic (MLCC), 22uF, ±20%, 6.3V, X7S, ±20%, SMD 0805; Manufacturer: TDK; Manufacturer Part Number: C2012X7S0J226MT000E
footprint CAP-0805 (0805 (2012M) Capacitor)
pins: 1, 2

## C2012X7S1A226MT000E
designator C?  Capacitance: 22uF  (hidden comment: *)
Capacitor, Ceramic (MLCC), 22uF, ±20%, 10V, X7S, ±20%, SMD 0805; Manufacturer: TDK; Manufacturer Part Number: C2012X7S1A226MT000E
footprint CAP-0805 (0805 (2012M) Capacitor)
pins: 1, 2

## C2012X7S1E106KT0A0E
designator C?  Capacitance: 10uF  (hidden comment: *)
Capacitor, Ceramic (MLCC), 10uF, ±10%, 25V, ±10%, SMD 0805; Manufacturer: TDK; Manufacturer Part Number: C2012X7S1E106KT0A0E
footprint CAP-0805 (0805 (2012M) Capacitor)
pins: 1, 2

## C2012X7S2A105KT000N
designator C?  Capacitance: 1uF  (hidden comment: *)
Capacitor, Ceramic (MLCC), 1uF, ±10%, 100V, X7S, ±10%, SMD 0805; Manufacturer: TDK; Manufacturer Part Number: C2012X7S2A105KT000N
footprint CAP-0805 (0805 (2012M) Capacitor)
pins: 1, 2

## C2012X7S2A224KT000N
designator C?  Capacitance: 220nF  (hidden comment: *)
Capacitor, Ceramic (MLCC), 220nF, ±10%, 100V, X7S, ±10%, SMD 0805; Manufacturer: TDK; Manufacturer Part Number: C2012X7S2A224KT000N
footprint CAP-0805 (0805 (2012M) Capacitor)
pins: 1, 2

## C2012X7S2A474KT000N
designator C?  Capacitance: 470nF  (hidden comment: *)
Capacitor, Ceramic (MLCC), 470nF, ±10%, 100V, X7S, ±10%, SMD 0805; Manufacturer: TDK; Manufacturer Part Number: C2012X7S2A474KT000N
footprint CAP-0805 (0805 (2012M) Capacitor)
pins: 1, 2

## C2012X7T2E104KT000N
designator C?  Capacitance: 100nF  (hidden comment: *)
Capacitor, Ceramic (MLCC), 100nF, ±10%, 250V, X7T, ±10%, SMD 0805; Manufacturer: TDK; Manufacturer Part Number: C2012X7T2E104KT000N
footprint CAP-0805 (0805 (2012M) Capacitor)
pins: 1, 2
